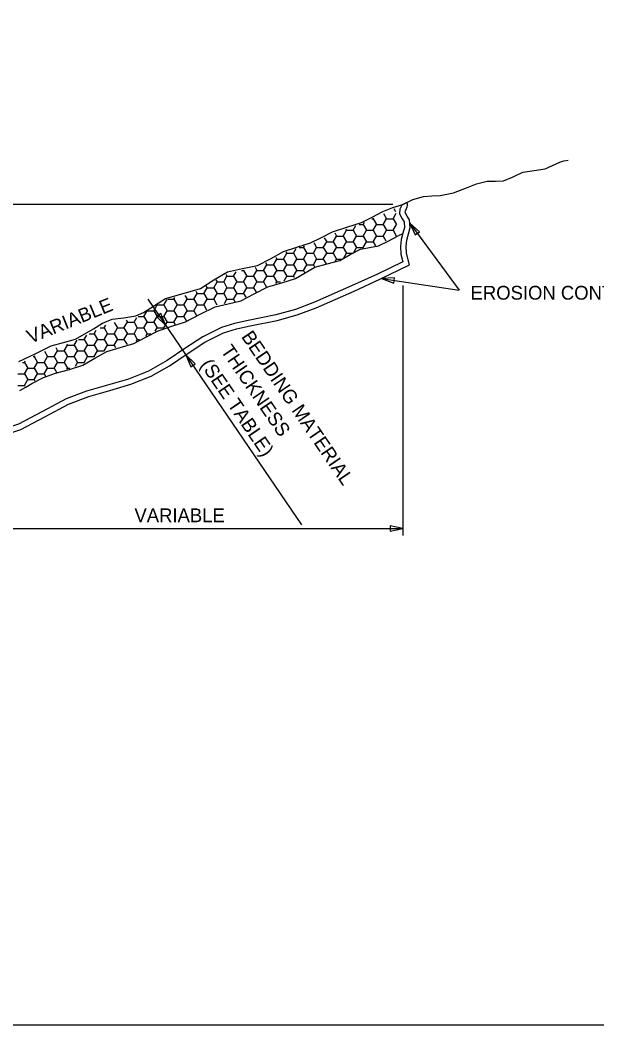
# Model space of a CAD drawing. Extents: x -439.1 to -407.9, y -458.1 to -436.2.
# Drawn here: x -425.67 to -419.41, y -458.05 to -447.12 of the extents above; entities that cross this region are included whole.
import ezdxf

# ---------------------------------------------------------------- set-up
doc = ezdxf.new("R2010")
doc.units = 0
doc.layers.add('Default', color=7, linetype='Continuous')
doc.layers.add('Draft_Named_Boundary', color=7, linetype='Continuous')

msp = doc.modelspace()

# ---------------------------------------------------------------- linework, layer by layer
at = {"layer": 'Default'}
for p, q in [((-421.625, -449.128), (-427.35, -449.128)), ((-421.613, -449.174), (-421.595, -449.206)), ((-421.523, -449.13), (-421.515, -449.128)), ((-421.472, -449.106), (-421.515, -449.128)), ((-421.851, -449.284), (-421.838, -449.284)), ((-421.838, -449.284), (-421.833, -449.276)), ((-421.838, -449.284), (-421.802, -449.347)), ((-421.73, -449.347), (-421.694, -449.284)), ((-421.727, -449.227), (-421.694, -449.284)), ((-421.694, -449.284), (-421.622, -449.284)), ((-421.622, -449.284), (-421.587, -449.224)), ((-421.622, -449.284), (-421.586, -449.347)), ((-422.163, -449.472), (-422.127, -449.409)), ((-422.135, -449.395), (-422.127, -449.409)), ((-422.127, -449.409), (-422.055, -449.409)), ((-422.055, -449.409), (-422.025, -449.358)), ((-422.055, -449.409), (-422.019, -449.472)), ((-421.991, -449.347), (-421.946, -449.347)), ((-421.946, -449.347), (-421.932, -449.322)), ((-421.946, -449.347), (-421.91, -449.409)), ((-421.946, -449.472), (-421.91, -449.409)), ((-421.91, -449.409), (-421.838, -449.409)), ((-421.838, -449.409), (-421.802, -449.347)), ((-421.838, -449.409), (-421.802, -449.472)), ((-421.802, -449.347), (-421.73, -449.347)), ((-421.73, -449.347), (-421.694, -449.409)), ((-421.73, -449.472), (-421.694, -449.409)), ((-421.694, -449.409), (-421.622, -449.409)), ((-421.622, -449.409), (-421.586, -449.347)), ((-421.622, -449.409), (-421.587, -449.47)), ((-421.44, -449.332), (-420.903, -450.062)), ((-422.369, -449.491), (-422.343, -449.534)), ((-422.271, -449.534), (-422.235, -449.472)), ((-422.255, -449.437), (-422.235, -449.472)), ((-422.235, -449.472), (-422.163, -449.472)), ((-422.163, -449.472), (-422.127, -449.534)), ((-422.055, -449.534), (-422.019, -449.472)), ((-422.019, -449.472), (-421.946, -449.472)), ((-421.946, -449.472), (-421.91, -449.534)), ((-421.838, -449.534), (-421.802, -449.472)), ((-421.802, -449.472), (-421.73, -449.472)), ((-421.73, -449.472), (-421.699, -449.526)), ((-422.704, -449.659), (-422.674, -449.607)), ((-422.643, -449.597), (-422.596, -449.597)), ((-422.596, -449.597), (-422.585, -449.577)), ((-422.596, -449.597), (-422.56, -449.659)), ((-422.488, -449.659), (-422.452, -449.597)), ((-422.483, -449.543), (-422.452, -449.597)), ((-422.452, -449.597), (-422.38, -449.597)), ((-422.38, -449.597), (-422.343, -449.534)), ((-422.38, -449.597), (-422.343, -449.659)), ((-422.343, -449.534), (-422.271, -449.534)), ((-422.271, -449.534), (-422.235, -449.597)), ((-422.271, -449.659), (-422.235, -449.597)), ((-422.235, -449.597), (-422.163, -449.597)), ((-422.163, -449.597), (-422.127, -449.534)), ((-422.163, -449.597), (-422.127, -449.659)), ((-422.127, -449.534), (-422.055, -449.534)), ((-422.055, -449.534), (-422.019, -449.597)), ((-422.053, -449.657), (-422.019, -449.597)), ((-422.019, -449.597), (-421.946, -449.597)), ((-421.946, -449.597), (-421.91, -449.534)), ((-421.946, -449.597), (-421.944, -449.602)), ((-421.91, -449.534), (-421.838, -449.534)), ((-421.838, -449.534), (-421.812, -449.579)), ((-422.921, -449.784), (-422.885, -449.722)), ((-422.896, -449.703), (-422.885, -449.722)), ((-422.885, -449.722), (-422.813, -449.722)), ((-422.813, -449.722), (-422.776, -449.659)), ((-422.813, -449.722), (-422.776, -449.784)), ((-422.785, -449.645), (-422.776, -449.659)), ((-422.776, -449.659), (-422.704, -449.659)), ((-422.704, -449.659), (-422.668, -449.722)), ((-422.704, -449.784), (-422.668, -449.722)), ((-422.668, -449.722), (-422.596, -449.722)), ((-422.596, -449.722), (-422.56, -449.659)), ((-422.596, -449.722), (-422.56, -449.784)), ((-422.56, -449.659), (-422.488, -449.659)), ((-422.488, -449.659), (-422.452, -449.722)), ((-422.488, -449.784), (-422.452, -449.722)), ((-422.452, -449.722), (-422.38, -449.722)), ((-422.38, -449.722), (-422.343, -449.659)), ((-422.38, -449.722), (-422.348, -449.776)), ((-422.343, -449.659), (-422.271, -449.659)), ((-422.271, -449.659), (-422.235, -449.722)), ((-422.25, -449.748), (-422.235, -449.722)), ((-422.235, -449.722), (-422.182, -449.722)), ((-422.155, -449.708), (-422.127, -449.659)), ((-422.127, -449.659), (-422.058, -449.659)), ((-423.268, -449.847), (-423.246, -449.847)), ((-423.246, -449.847), (-423.242, -449.841)), ((-423.246, -449.847), (-423.209, -449.909)), ((-423.137, -449.909), (-423.101, -449.847)), ((-423.121, -449.812), (-423.101, -449.847)), ((-423.101, -449.847), (-423.029, -449.847)), ((-423.029, -449.847), (-422.993, -449.784)), ((-423.029, -449.847), (-422.993, -449.909)), ((-423.007, -449.761), (-422.993, -449.784)), ((-422.993, -449.784), (-422.921, -449.784)), ((-422.921, -449.784), (-422.885, -449.847)), ((-422.921, -449.909), (-422.885, -449.847)), ((-422.885, -449.847), (-422.813, -449.847)), ((-422.813, -449.847), (-422.776, -449.784)), ((-422.813, -449.847), (-422.776, -449.909)), ((-422.776, -449.784), (-422.704, -449.784)), ((-422.704, -449.784), (-422.668, -449.847)), ((-422.704, -449.909), (-422.668, -449.847)), ((-422.668, -449.847), (-422.596, -449.847)), ((-422.596, -449.847), (-422.56, -449.784)), ((-422.596, -449.847), (-422.583, -449.87)), ((-422.56, -449.784), (-422.488, -449.784)), ((-422.488, -449.784), (-422.47, -449.815)), ((-423.547, -449.95), (-423.534, -449.972)), ((-423.462, -449.972), (-423.426, -449.909)), ((-423.438, -449.888), (-423.426, -449.909)), ((-423.426, -449.909), (-423.354, -449.909)), ((-423.354, -449.909), (-423.325, -449.86)), ((-423.354, -449.909), (-423.318, -449.972)), ((-423.246, -449.972), (-423.209, -449.909)), ((-423.209, -449.909), (-423.137, -449.909)), ((-423.137, -449.909), (-423.101, -449.972)), ((-423.029, -449.972), (-422.993, -449.909)), ((-422.993, -449.909), (-422.921, -449.909)), ((-422.921, -449.909), (-422.885, -449.972)), ((-422.805, -449.958), (-422.776, -449.909)), ((-422.776, -449.909), (-422.704, -449.909)), ((-422.704, -449.909), (-422.697, -449.922)), ((-421.747, -449.934), (-420.903, -450.062)), ((-423.765, -450.072), (-423.751, -450.097)), ((-423.679, -450.097), (-423.642, -450.034)), ((-423.656, -450.011), (-423.642, -450.034)), ((-423.642, -450.034), (-423.57, -450.034)), ((-423.57, -450.034), (-423.534, -449.972)), ((-423.57, -450.034), (-423.534, -450.097)), ((-423.534, -449.972), (-423.462, -449.972)), ((-423.462, -449.972), (-423.426, -450.034)), ((-423.462, -450.097), (-423.426, -450.034)), ((-423.426, -450.034), (-423.354, -450.034)), ((-423.354, -450.034), (-423.318, -449.972)), ((-423.354, -450.034), (-423.318, -450.097)), ((-423.318, -449.972), (-423.246, -449.972)), ((-423.246, -449.972), (-423.209, -450.034)), ((-423.246, -450.097), (-423.209, -450.034)), ((-423.209, -450.034), (-423.137, -450.034)), ((-423.137, -450.034), (-423.101, -449.972)), ((-423.137, -450.034), (-423.11, -450.082)), ((-423.101, -449.972), (-423.029, -449.972)), ((-423.029, -449.972), (-422.997, -450.027)), ((-422.894, -449.988), (-422.885, -449.972)), ((-422.885, -449.972), (-422.846, -449.972)), ((-421.515, -450.009), (-421.515, -452.73)), ((-424.286, -450.159), (-422.615, -452.612)), ((-424.112, -450.222), (-424.076, -450.161)), ((-424.07, -450.159), (-424.003, -450.159)), ((-424.003, -450.159), (-423.993, -450.142)), ((-424.003, -450.159), (-423.967, -450.222)), ((-423.895, -450.222), (-423.859, -450.159)), ((-423.883, -450.118), (-423.859, -450.159)), ((-423.859, -450.159), (-423.787, -450.159)), ((-423.787, -450.159), (-423.751, -450.097)), ((-423.787, -450.159), (-423.751, -450.222)), ((-423.751, -450.097), (-423.679, -450.097)), ((-423.679, -450.097), (-423.642, -450.159)), ((-423.679, -450.222), (-423.642, -450.159)), ((-423.642, -450.159), (-423.57, -450.159)), ((-423.57, -450.159), (-423.534, -450.097)), ((-423.57, -450.159), (-423.536, -450.22)), ((-423.534, -450.097), (-423.462, -450.097)), ((-423.462, -450.097), (-423.426, -450.159)), ((-423.452, -450.205), (-423.426, -450.159)), ((-423.426, -450.159), (-423.354, -450.159)), ((-423.354, -450.159), (-423.318, -450.097)), ((-423.354, -450.159), (-423.339, -450.185)), ((-423.318, -450.097), (-423.246, -450.097)), ((-423.246, -450.097), (-423.222, -450.138)), ((-424.328, -450.347), (-424.292, -450.285)), ((-424.292, -450.284), (-424.22, -450.284)), ((-424.22, -450.284), (-424.184, -450.222)), ((-424.22, -450.284), (-424.184, -450.347)), ((-424.186, -450.218), (-424.184, -450.222)), ((-424.184, -450.222), (-424.112, -450.222)), ((-424.112, -450.222), (-424.075, -450.284)), ((-424.112, -450.347), (-424.075, -450.284)), ((-424.075, -450.284), (-424.003, -450.284)), ((-424.003, -450.284), (-423.967, -450.222)), ((-424.003, -450.284), (-423.967, -450.347)), ((-423.967, -450.222), (-423.895, -450.222)), ((-423.895, -450.222), (-423.859, -450.284)), ((-423.895, -450.347), (-423.859, -450.284)), ((-423.859, -450.284), (-423.787, -450.284)), ((-423.787, -450.284), (-423.751, -450.222)), ((-423.787, -450.284), (-423.757, -450.336)), ((-423.751, -450.222), (-423.679, -450.222)), ((-423.679, -450.222), (-423.648, -450.275)), ((-424.521, -450.388), (-424.508, -450.409)), ((-424.436, -450.409), (-424.406, -450.357)), ((-424.391, -450.347), (-424.328, -450.347)), ((-424.328, -450.347), (-424.292, -450.409)), ((-424.22, -450.409), (-424.184, -450.347)), ((-424.184, -450.347), (-424.112, -450.347)), ((-424.112, -450.347), (-424.075, -450.409)), ((-424.003, -450.409), (-423.967, -450.347)), ((-423.967, -450.347), (-423.895, -450.347)), ((-423.895, -450.347), (-423.866, -450.397)), ((-424.869, -450.534), (-424.846, -450.495)), ((-424.803, -450.472), (-424.761, -450.472)), ((-424.761, -450.472), (-424.743, -450.44)), ((-424.761, -450.472), (-424.725, -450.534)), ((-424.653, -450.534), (-424.617, -450.472)), ((-424.651, -450.413), (-424.617, -450.472)), ((-424.617, -450.472), (-424.545, -450.472)), ((-424.545, -450.472), (-424.508, -450.409)), ((-424.545, -450.472), (-424.508, -450.534)), ((-424.508, -450.409), (-424.436, -450.409)), ((-424.436, -450.409), (-424.4, -450.472)), ((-424.436, -450.534), (-424.4, -450.472)), ((-424.4, -450.472), (-424.328, -450.472)), ((-424.328, -450.472), (-424.292, -450.409)), ((-424.328, -450.472), (-424.292, -450.534)), ((-424.292, -450.409), (-424.22, -450.409)), ((-424.22, -450.409), (-424.184, -450.472)), ((-424.205, -450.508), (-424.184, -450.472)), ((-424.184, -450.472), (-424.112, -450.472)), ((-424.111, -450.472), (-424.075, -450.409)), ((-424.085, -450.44), (-424.091, -450.445)), ((-424.075, -450.409), (-424.003, -450.409)), ((-424.003, -450.409), (-423.988, -450.436)), ((-425.086, -450.659), (-425.054, -450.604)), ((-425.04, -450.597), (-424.978, -450.597)), ((-424.978, -450.597), (-424.95, -450.55)), ((-424.978, -450.597), (-424.941, -450.659)), ((-424.922, -450.534), (-424.869, -450.534)), ((-424.869, -450.534), (-424.833, -450.597)), ((-424.869, -450.659), (-424.833, -450.597)), ((-424.833, -450.597), (-424.761, -450.597)), ((-424.761, -450.597), (-424.725, -450.534)), ((-424.761, -450.597), (-424.725, -450.659)), ((-424.725, -450.534), (-424.653, -450.534)), ((-424.653, -450.534), (-424.617, -450.597)), ((-424.653, -450.659), (-424.617, -450.597)), ((-424.617, -450.597), (-424.545, -450.597)), ((-424.545, -450.597), (-424.508, -450.534)), ((-424.545, -450.597), (-424.512, -450.653)), ((-424.508, -450.534), (-424.436, -450.534)), ((-424.436, -450.534), (-424.4, -450.597)), ((-424.41, -450.614), (-424.4, -450.597)), ((-424.4, -450.597), (-424.377, -450.597)), ((-424.307, -450.561), (-424.292, -450.534)), ((-424.292, -450.534), (-424.255, -450.534)), ((-425.408, -450.726), (-425.375, -450.784)), ((-425.302, -450.784), (-425.266, -450.722)), ((-425.287, -450.686), (-425.266, -450.722)), ((-425.266, -450.722), (-425.194, -450.722)), ((-425.194, -450.722), (-425.158, -450.659)), ((-425.194, -450.722), (-425.158, -450.784)), ((-425.166, -450.646), (-425.158, -450.659)), ((-425.158, -450.659), (-425.086, -450.659)), ((-425.086, -450.659), (-425.05, -450.722)), ((-425.086, -450.784), (-425.05, -450.722)), ((-425.05, -450.722), (-424.978, -450.722)), ((-424.978, -450.722), (-424.941, -450.659)), ((-424.978, -450.722), (-424.941, -450.784)), ((-424.941, -450.659), (-424.869, -450.659)), ((-424.869, -450.659), (-424.833, -450.722)), ((-424.869, -450.784), (-424.833, -450.722)), ((-424.833, -450.722), (-424.762, -450.722)), ((-424.761, -450.721), (-424.725, -450.659)), ((-424.725, -450.659), (-424.653, -450.659)), ((-424.653, -450.659), (-424.638, -450.685)), ((-425.627, -450.847), (-425.618, -450.831)), ((-425.531, -450.784), (-425.519, -450.784)), ((-425.519, -450.784), (-425.513, -450.775)), ((-425.519, -450.784), (-425.483, -450.847)), ((-425.411, -450.847), (-425.375, -450.784)), ((-425.375, -450.784), (-425.302, -450.784)), ((-425.302, -450.784), (-425.266, -450.847)), ((-425.194, -450.847), (-425.158, -450.784)), ((-425.158, -450.784), (-425.086, -450.784)), ((-425.086, -450.784), (-425.05, -450.847)), ((-424.978, -450.847), (-424.941, -450.784)), ((-424.941, -450.784), (-424.869, -450.784)), ((-424.869, -450.784), (-424.868, -450.787)), ((-423.868, -450.759), (-423.874, -450.764)), ((-425.647, -450.847), (-425.627, -450.847)), ((-425.627, -450.847), (-425.591, -450.909)), ((-425.627, -450.972), (-425.591, -450.909)), ((-425.591, -450.909), (-425.519, -450.909)), ((-425.519, -450.909), (-425.483, -450.847)), ((-425.519, -450.909), (-425.483, -450.972)), ((-425.483, -450.847), (-425.411, -450.847)), ((-425.411, -450.847), (-425.375, -450.909)), ((-425.411, -450.972), (-425.375, -450.909)), ((-425.375, -450.909), (-425.302, -450.909)), ((-425.302, -450.909), (-425.266, -450.847)), ((-425.302, -450.909), (-425.273, -450.96)), ((-425.266, -450.847), (-425.194, -450.847)), ((-425.194, -450.847), (-425.158, -450.909)), ((-425.164, -450.92), (-425.158, -450.909)), ((-425.158, -450.909), (-425.134, -450.909)), ((-425.073, -450.888), (-425.05, -450.847)), ((-425.05, -450.847), (-424.978, -450.847)), ((-424.978, -450.847), (-424.975, -450.852)), ((-425.699, -450.972), (-425.627, -450.972)), ((-425.627, -450.972), (-425.591, -451.034)), ((-425.627, -451.097), (-425.591, -451.034)), ((-425.591, -451.034), (-425.519, -451.034)), ((-425.519, -451.034), (-425.483, -450.972)), ((-425.519, -451.034), (-425.512, -451.046)), ((-425.483, -450.972), (-425.411, -450.972)), ((-425.411, -450.972), (-425.393, -451.003)), ((-425.699, -451.097), (-425.627, -451.097)), ((-425.627, -451.097), (-425.622, -451.105)), ((-426.203, -452.652), (-421.515, -452.652))]:
    msp.add_line(p, q, dxfattribs=at)
for points in [[(-421.515, -449.128), (-421.408, -449.074), (-421.292, -449.042), (-421.202, -449.035), (-421.112, -449.031), (-420.967, -449.001), (-420.826, -448.948), (-420.714, -448.903), (-420.6, -448.877), (-420.509, -448.877), (-420.421, -448.871), (-420.317, -448.827), (-420.213, -448.778), (-420.09, -448.76), (-419.969, -448.743), (-419.89, -448.707), (-419.81, -448.669), (-419.766, -448.656), (-419.72, -448.647)], [(-425.688, -450.837), (-425.511, -450.752), (-425.335, -450.665), (-425.203, -450.63), (-425.072, -450.594), (-424.875, -450.48), (-424.778, -450.42), (-424.675, -450.378), (-424.545, -450.36), (-424.416, -450.339), (-424.332, -450.303), (-424.253, -450.252), (-424.093, -450.152), (-423.903, -450.098), (-423.715, -450.043), (-423.568, -449.949), (-423.419, -449.86), (-423.258, -449.824), (-423.095, -449.791), (-422.953, -449.719), (-422.813, -449.641), (-422.667, -449.593), (-422.52, -449.547), (-422.4, -449.487), (-422.28, -449.425), (-422.123, -449.375), (-421.966, -449.326), (-421.849, -449.267), (-421.733, -449.206), (-421.626, -449.163), (-421.515, -449.128)], [(-421.523, -449.13), (-421.547, -449.181), (-421.551, -449.229), (-421.529, -449.274), (-421.502, -449.319), (-421.497, -449.38), (-421.515, -449.441)], [(-421.472, -449.519), (-421.435, -449.381), (-421.443, -449.297), (-421.469, -449.256), (-421.49, -449.216), (-421.486, -449.193), (-421.485, -449.191)], [(-421.485, -449.191), (-421.468, -449.156), (-421.464, -449.141), (-421.466, -449.124), (-421.472, -449.106)], [(-425.677, -451.151), (-425.61, -451.115), (-425.546, -451.075), (-425.421, -451.01), (-425.288, -450.962), (-425.138, -450.925), (-424.993, -450.877), (-424.863, -450.801), (-424.732, -450.728), (-424.585, -450.685), (-424.437, -450.642), (-424.306, -450.573), (-424.175, -450.502), (-424.026, -450.454), (-423.876, -450.407), (-423.717, -450.322), (-423.556, -450.243), (-423.415, -450.21), (-423.276, -450.176), (-423.129, -450.1), (-422.983, -450.023), (-422.83, -449.981), (-422.681, -449.935), (-422.577, -449.872), (-422.472, -449.812), (-422.336, -449.776), (-422.2, -449.739), (-422.089, -449.674), (-421.977, -449.615), (-421.878, -449.597), (-421.779, -449.579), (-421.675, -449.529), (-421.573, -449.472), (-421.547, -449.46), (-421.52, -449.45)], [(-421.515, -449.441), (-421.534, -449.51), (-421.542, -449.581), (-421.537, -449.668), (-421.515, -449.753)], [(-421.443, -449.787), (-421.475, -449.659), (-421.48, -449.583), (-421.472, -449.519)], [(-421.515, -449.753), (-421.792, -449.887), (-422.072, -450.015), (-422.476, -450.193), (-422.682, -450.27), (-422.895, -450.33), (-423.195, -450.389), (-423.343, -450.422), (-423.486, -450.467), (-423.69, -450.568), (-423.884, -450.694), (-424.077, -450.825), (-424.277, -450.94), (-424.496, -451.027), (-424.724, -451.095), (-424.952, -451.161), (-425.173, -451.244), (-425.43, -451.382), (-425.689, -451.518), (-425.941, -451.599), (-426.203, -451.647)], [(-426.195, -451.709), (-425.924, -451.66), (-425.664, -451.575), (-425.405, -451.44), (-425.147, -451.301), (-424.926, -451.218), (-424.698, -451.151), (-424.47, -451.084), (-424.25, -450.997), (-424.051, -450.882), (-423.859, -450.752), (-423.666, -450.626), (-423.463, -450.526), (-423.322, -450.481), (-423.176, -450.449), (-422.881, -450.391), (-422.665, -450.33), (-422.456, -450.252), (-422.046, -450.071), (-421.765, -449.943), (-421.443, -449.787)]]:
    msp.add_lwpolyline(points, dxfattribs=at)
for points in [[(-421.335, -449.427), (-421.44, -449.332), (-421.381, -449.461)], [(-421.335, -449.427), (-421.44, -449.332), (-421.381, -449.461)], [(-421.606, -449.927), (-421.747, -449.934), (-421.615, -449.983)], [(-421.606, -449.927), (-421.747, -449.934), (-421.615, -449.983)], [(-424.193, -450.346), (-424.091, -450.445), (-424.145, -450.314)], [(-424.193, -450.346), (-424.091, -450.445), (-424.145, -450.314)], [(-423.772, -450.862), (-423.874, -450.764), (-423.82, -450.894)], [(-423.772, -450.862), (-423.874, -450.764), (-423.82, -450.894)], [(-421.654, -452.681), (-421.515, -452.652), (-421.654, -452.623)]]:
    msp.add_lwpolyline(points, close=True, dxfattribs=at)
at = {"layer": 'Draft_Named_Boundary'}
msp.add_lwpolyline([(-439.109, -458.051), (-407.859, -458.051), (-407.859, -437.676), (-439.109, -437.676)], close=True, dxfattribs=at)

# ---------------------------------------------------------------- texts
at = {"layer": 'Default'}
for s, p in [('EROSION CONTROL GEOTEXTILE', (-420.78, -450.164)), ('VARIABLE', (-424.431, -452.584))]:
    msp.add_text(s, height=0.15, dxfattribs=at).set_placement(p)
for s, rotation, p in [('VARIABLE', 22, (-425.562, -450.644)), ('BEDDING MATERIAL ', 304.3, (-423.276, -450.567)), ('THICKNESS ', 304.3, (-423.499, -450.72)), ('(SEE TABLE)', 304.3, (-423.722, -450.872))]:
    msp.add_text(s, height=0.15, rotation=rotation, dxfattribs=at).set_placement(p)

doc.saveas('drawing.dxf')
